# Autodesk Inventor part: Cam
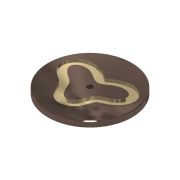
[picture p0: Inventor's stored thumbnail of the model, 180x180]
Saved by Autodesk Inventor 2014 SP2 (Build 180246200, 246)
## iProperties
Created: 2016-02
Part Number: Cam
Material: Steel
Document SubType Name: Modeling
Designer: User
Manufacturer: Standard
Standards Organization: Custom
Density: 7.85 g/cm^3
Appearance: Gunmetal - Antique Polished
CustomPartVersion: 1
Author: User
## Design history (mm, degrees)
sketch "Main Sketch" dims "d24" = 3
  geometry: 61 further points
  constraints: 63 other
extrude "Cam" new body sketch "Main Sketch" taper "d1" = 0 deg; distance "da_bv" = 7
sketch "Sketch2" dims "d25" = 16
  geometry: C1 r 87.5 at (0, 0); 3 further points
  constraints: 1 centre point, 1 coincident, 3 other
  dimensions: "d4" = 175 diameter of C1
extrude "Extrusion2" join sketch "Sketch2" distance "d6" = 7; taper "d7" = 0 deg
sketch "Sketch3"
  geometry: C1 r 87.5 at (0, 0) reference; 2 further points
extrude "Extrusion3" join sketch "Sketch3" distance "d8" = 5; taper "d9" = 0 deg
hole "Hole1" diameter "d12" = 12; stored, may be unused: countersink angle "d16" = 90 deg, drill point angle "d18" = 118 deg; dims "d10" = 10, "d11" = 10, "d13" = 6, "d14" = 4, "d15" = 2, "d17" = 8
chamfer "Chamfer1" distance "d19" = 1; stored, may be unused: second distance "d20" = 2, angle "d21" = 45 deg
body "Solid1"
